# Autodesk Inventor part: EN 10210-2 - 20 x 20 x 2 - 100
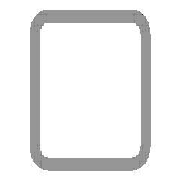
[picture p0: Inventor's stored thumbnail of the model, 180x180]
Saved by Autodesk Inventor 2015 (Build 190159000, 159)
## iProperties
Created: 2015-05
Part Number: EN 10210-2 - 20 x 20 x 2 - 100
Material: Steel, Mild
Description: Tube
Document SubType Name: Modeling
Standard: DIN
Designer: TREINA6
Standard Revision: 1997
Standards Organization: DIN
Language: en-US
Size Designation: 20 x 20 x 2
Categories: <MemberInstance><Categories><Category DisplayName="Structural Shapes" InternalName="089c4875-fa83-4c05-b084-43b9cc11f5ed" Mnemonic="GRDR"><CategoryParameter Dis
Stock Number: 20 x 20 x 2
Density: 7.85 g/cm^3
Appearance: Semi-Polished
_CCFamilyMember: 1
_CCFamilyDisplayName: DIN EN 10210-2 (Square) - Tube
_FrameMemberDoc: Frame Member File
_Version: 15.0.0
_GetPNFromCC: 1
IsCustomPart: 1
Author: TREINA6
G_L: 100,000 mm
G_W: 20,000 mm
G_H: 20,000 mm
+416ED0BE-771C-4462-B551-5CEA9B5C91F3+CUTDETAIL1: Miter 45,00 deg
+92CAF834-4A3A-427E-AD43-0E28CC12F767+CUTDETAIL2: Miter 45,00 deg
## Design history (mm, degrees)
node "Start plane"
node "End plane"
sketch "Sketch"
  geometry: L1 (-10, -7)-(-10, 7); L2 (-7, 10)-(7, 10); L3 (10, 7)-(10, -7); L4 (7, -10)-(-7, -10); L5 (-7, 8)-(7, 8); L6 (8, 7)-(8, -7); L7 (7, -8)-(-7, -8); L8 (-8, -7)-(-8, 7); L9 (0, 14.87)-(0, -14.87) reference; L10 (-14.87, 0)-(14.87, 0) reference; A1 r 3 centre (-7, -7) between (-10, -7) and (-7, -10); A2 r 3 centre (-7, 7) between (-7, 10) and (-10, 7); A3 r 3 centre (7, 7) between (10, 7) and (7, 10); A4 r 3 centre (7, -7) between (7, -10) and (10, -7); A5 r 1 centre (-7, 7) between (-7, 8) and (-8, 7); A6 r 1 centre (7, 7) between (8, 7) and (7, 8); A7 r 1 centre (7, -7) between (7, -8) and (8, -7); A8 r 1 centre (-7, -7) between (-8, -7) and (-7, -8)
  constraints: 16 end point, 16 point on circle, 8 centre point, 8 tangent, 4 parallel, 3 equal radius, 2 perpendicular, 7 other
  dimensions: "d7" = 3 radius of A1 (= G_IR); "d10" = 20 distance between parallel lines of L2 L4 (= G_H); "d11" = 20 distance between parallel lines of L1 L3 (= G_W); "d12" = 2 distance between parallel lines of L3 L6 (= G_T); "d15" = 10 distance between parallel lines of L2 L10 (= 0.5 x d10); "d16" = 10 distance between parallel lines of L9 L3 (= 0.5 x d11)
extrude "Body" new body sketch "Sketch" stored distance "d3" = 100 (= G_L); taper "d4" = 0 deg
node "Driven Length"
  sketch "Sketch3"
    geometry: L1 (0, 0)-(10, 0) reference
    constraints: 2 end point, 1 horizontal
  workplane "Work Plane3"
  sketch "Sketch4"
    geometry: L1 (-2, 0)-(12, 0) reference; L2 (-2, 100)-(12, 100) reference
    dimensions: "d18" = 100 distance between parallel lines of L1 L2 (derived)
workplane "Work Plane4"
split "Split1"
workplane "Work Plane5"
split "Split2"
body "Solid1"
other parameters: "G_W" = 20 [user parameter; used in 1 equation term], "G_H" = 20 [user parameter; used in 1 equation term], "G_T" = 2 [user parameter; used in 1 equation term], "G_IR" = 3 [user parameter; used in 1 equation term], "G_L" = 100 (= d18) [user parameter; used in 1 equation term], "G_OFFSET_START" = 0 [user parameter; used in 1 equation term], "G_OFFSET_END" = 0 [user parameter; used in 1 equation term], "d13" = 0 (computed from G_OFFSET_START), "d17" = 90 deg
